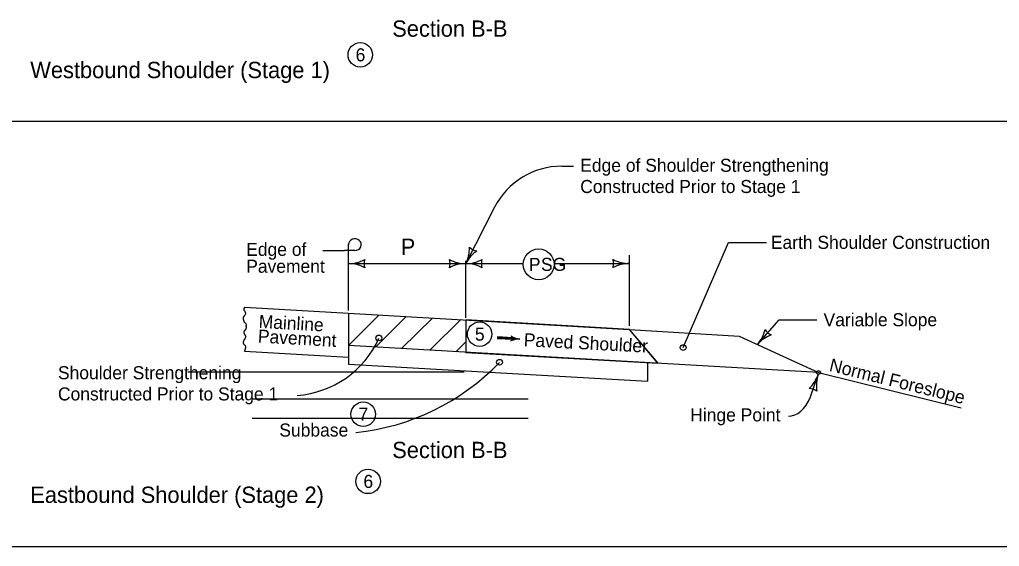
# Model space of a CAD drawing. Extents: x 6410 to 81668, y 3928 to 11667.
# Drawn here: x 7264 to 8465, y 8314 to 8961 of the extents above; entities that cross this region are included whole.
import ezdxf

# ---------------------------------------------------------------- set-up
doc = ezdxf.new("R2010")
doc.units = 0
for name, color, linetype in [('dsnNonPlotable', 7, 'Continuous'), ('dsnStdBlockModified', 7, 'Continuous'), ('dsnStdSection', 7, 'Continuous'), ('Level 11', 7, 'Continuous'), ('Level 14', 7, 'Continuous'), ('Level 3', 7, 'Continuous'), ('Level 7', 7, 'Continuous')]:
    doc.layers.add(name, color=color, linetype=linetype)

msp = doc.modelspace()

# ---------------------------------------------------------------- linework, layer by layer
at = {"layer": 'dsnNonPlotable'}
msp.add_line((6410.4, 8314.4), (9506.1, 8314.4), dxfattribs=at)
at = {"layer": 'dsnStdBlockModified'}
for p, q in [((7539.5, 8607.8), (7667, 8600.4)), ((7667, 8600.4), (7667, 8546.4)), ((7667, 8600.4), (8011.2, 8580.4)), ((7810.7, 8592.1), (7810.7, 8552.2)), ((8010.8, 8580.6), (8010.8, 8580.6)), ((8011.2, 8580.4), (8046.3, 8539)), ((8011.3, 8580.5), (8146, 8572.1)), ((8146, 8572.1), (8243.1, 8527.6)), ((7539.5, 8553.8), (7667, 8546.4)), ((8243.1, 8527.6), (7667, 8560.8)), ((8033.5, 8554.1), (8033.5, 8554.1)), ((7667, 8546.4), (7667, 8538)), ((7667, 8538), (8033.5, 8516.9)), ((8033.5, 8539.7), (8033.5, 8516.9)), ((7470.2, 8528.5), (7808.7, 8528.5)), ((8243.1, 8527.6), (8418, 8484.3)), ((7548.9, 8495.5), (7887.4, 8495.5)), ((7548.9, 8471.8), (7887.4, 8471.8))]:
    msp.add_line(p, q, dxfattribs=at)
msp.add_ellipse((8243.1, 8527.6), major_axis=(2.58, 0), ratio=0.913811, dxfattribs=at)
for points in [[(7539.5, 8607.8), (7539, 8604.2), (7540, 8602.7), (7540.9, 8600.4), (7540.3, 8598.4), (7538.4, 8596), (7537.9, 8594.1), (7538.4, 8591.8), (7539.2, 8589.4), (7540.3, 8588.7), (7541.7, 8586.2), (7541.7, 8585.3)], [(7539.7, 8568.2), (7539.9, 8568.5), (7540.1, 8568.7), (7540.5, 8569.3), (7540.7, 8569.9), (7540.9, 8570.2), (7541, 8570.5), (7541.1, 8571.1), (7541.1, 8571.7), (7541.1, 8572.3), (7541, 8572.6), (7541, 8572.7), (7541, 8572.9), (7540.7, 8573.2), (7540.5, 8573.6), (7540.2, 8574), (7539.9, 8574.4), (7539.8, 8574.7), (7539.6, 8574.9), (7539.4, 8575.5), (7539.2, 8576.1), (7539.1, 8576.4), (7539, 8576.7), (7539, 8576.8), (7539, 8576.9), (7539.2, 8577.7), (7539.4, 8578.2), (7539.7, 8578.7), (7540.1, 8579.4), (7540.6, 8579.9), (7541.1, 8580.5), (7541.4, 8580.8), (7541.6, 8581.1), (7541.8, 8581.6), (7541.9, 8582.1), (7542, 8582.5), (7542.1, 8582.8), (7542.1, 8582.9), (7542.1, 8583), (7542, 8583.5), (7541.9, 8584), (7541.8, 8584.2), (7541.8, 8584.3), (7541.7, 8584.4), (7541.7, 8584.5), (7541.7, 8585.3)], [(7539.7, 8568.2), (7539.5, 8568), (7539.2, 8567.8), (7539, 8567.5), (7538.8, 8567.2), (7538.7, 8567), (7538.5, 8566.7), (7538.3, 8566.1), (7538.2, 8565.8), (7538.1, 8565.5), (7538, 8565.2), (7538, 8565.1), (7538, 8564.9), (7538, 8564.4), (7538.1, 8563.9), (7538.3, 8563.4), (7538.6, 8562.9), (7539, 8562.2), (7539.5, 8561.7), (7540, 8561.2), (7540.3, 8560.8), (7540.5, 8560.5), (7540.9, 8559.6), (7541, 8559.1), (7541, 8558.6), (7541, 8558.3), (7540.9, 8558), (7540.9, 8557.7), (7540.8, 8557.5), (7540.5, 8556.3), (7540.3, 8555.7), (7540.1, 8555.1), (7539.9, 8554.5), (7539.7, 8554.2), (7539.6, 8553.9), (7539.5, 8553.8)]]:
    msp.add_spline(points, degree=3, dxfattribs=at)
at = {"layer": 'dsnStdSection'}
for p, q in [((7928.4, 8780.7), (7942.7, 8780.7)), ((7846.1, 8730.3), (7810.7, 8661.2)), ((7667, 8664.5), (7667, 8685.3)), ((8077.2, 8558.2), (8132.9, 8687.3)), ((8132.9, 8687.3), (8179.3, 8687.3)), ((7635.6, 8677.3), (7662.3, 8677.3)), ((7674.8, 8677.3), (7662.3, 8677.3)), ((8011.3, 8585), (8011.3, 8671.7)), ((7667, 8603.6), (7667, 8664.5)), ((7667, 8661.2), (7881.3, 8661.2)), ((7810.7, 8594.9), (7810.7, 8664.5)), ((7919.1, 8661.3), (8011.3, 8661.3)), ((7667, 8560.8), (7704.7, 8598.2)), ((7700, 8558.9), (7737.8, 8596.3)), ((7732.2, 8557.1), (7770, 8594.5)), ((7766.8, 8555.1), (7804.6, 8592.5)), ((8168.2, 8561.9), (8194.8, 8592.4)), ((8194.8, 8592.4), (8241.2, 8592.4)), ((7798.5, 8553.2), (7810.7, 8565.4)), ((7868, 8569.3), (7849.8, 8570.4)), ((7867.9, 8568.4), (7867.9, 8568.4)), ((7868, 8570.3), (7868, 8570.3)), ((8233.3, 8497.7), (8242.8, 8525.3))]:
    msp.add_line(p, q, dxfattribs=at)
for points in [[(7868, 8570.3), (7849.8, 8571.3), (7849.7, 8569.4), (7867.9, 8568.4), (7867.9, 8570), (7850.1, 8571.1), (7850, 8569.6), (7867.5, 8568.6), (7867.6, 8569.8), (7850.3, 8570.8), (7850.3, 8569.8), (7867.3, 8568.8), (7867.4, 8569.5), (7850.5, 8570.6), (7850.5, 8570), (7867.1, 8569.1)], [(7867.6, 8571.5), (7868.3, 8570.3), (7868.3, 8568.7), (7867.5, 8567.3), (7870.3, 8568.2), (7873.5, 8568.8), (7874.4, 8568.9), (7872.1, 8569.5), (7868.9, 8570.7), (7868, 8571.3), (7868.1, 8567.7), (7873, 8569), (7868.4, 8570.5), (7868.4, 8568.1), (7871.8, 8569.1), (7868.8, 8569.9), (7868.6, 8568.5), (7870.7, 8569), (7869.1, 8569.5), (7869, 8568.9), (7869.8, 8569)]]:
    msp.add_lwpolyline(points, dxfattribs=at)
msp.add_circle((7900.2, 8660.3), 18.9, dxfattribs=at)
for centre, radius, start, end in [((7928.4, 8688.3), 92.4, 90, 152.9341), ((7772.9, 8680.5), 42.5, 332.9341, 1.0066), ((7848.6, 8641.8), 42.5, 124.8616, 152.9341), ((7826.9, 8692.9), 16.4, 225.2008, 260.6675), ((7667, 8703.7), 42.5, 270, 298.0725), ((7667, 8618.7), 42.5, 61.9275, 90), ((7702.6, 8661.2), 16.4, 162.2666, 197.7334), ((7775.1, 8661.2), 16.4, 342.2666, 17.7334), ((7810.7, 8703.7), 42.5, 241.9275, 270), ((7810.7, 8618.7), 42.5, 90, 118.0725), ((7810.7, 8703.7), 42.5, 270, 298.0725), ((7810.7, 8618.7), 42.5, 61.9275, 90), ((7846.3, 8661.2), 16.4, 162.2666, 197.7334), ((7975.6, 8661.3), 16.4, 342.2666, 17.7333), ((8011.3, 8703.8), 42.5, 241.9275, 270), ((8011.3, 8618.8), 42.5, 90, 118.0725), ((8136.2, 8589.9), 42.5, 318.8454, 346.9178), ((8191.6, 8588.8), 16.4, 211.112, 246.5787), ((7595.7, 8618.2), 118.9, 274.0851, 336.0699), ((8200.2, 8534), 42.5, 110.7729, 138.8454), ((7648.2, 8734.9), 282, 275.6784, 316.2844), ((8202.6, 8539.1), 42.5, 312.9788, 341.0513), ((8283, 8511.5), 42.5, 161.0513, 189.1238), ((8231.2, 8491.6), 16.4, 53.3179, 88.7846)]:
    msp.add_arc(centre, radius, start, end, dxfattribs=at)
for centre, major_axis, ratio, start_param, end_param in [((7674.8, 8684.5), (-7.81, 0), 0.913811, 1.570796, 6.283185), ((7864.2, 8569.5), (3.88, 0), 0.913811, 5.202895, 7.237436), ((7876.5, 8548.5), (22.2, 0), 0.913811, 1.537172, 2.061295), ((7879.3, 8588.9), (-22.2, 0), 0.913811, 0.954258, 1.478381), ((8206.2, 8535.5), (0, 61.5), 0.559383, 3.141593, 4.048985)]:
    msp.add_ellipse(centre, major_axis=major_axis, ratio=ratio, start_param=start_param, end_param=end_param, dxfattribs=at)
at = {"layer": 'Level 11'}
msp.add_line((8566, 8835.4), (6410.4, 8835.4), dxfattribs=at)
at = {"layer": 'Level 14'}
for centre in [(7704.3, 8570), (7704.3, 8570), (8077.2, 8558.2), (8077.2, 8558.2), (7852.2, 8540.2), (7852.2, 8540.2)]:
    msp.add_circle(centre, 3.54, dxfattribs=at)
at = {"layer": 'Level 3'}
for p, q in [((7810.8, 8592.1), (7810.7, 8552.2)), ((8011.3, 8580.5), (7810.8, 8592.1)), ((8046.3, 8539), (8011.3, 8580.5)), ((7810.7, 8552.2), (8046.3, 8539))]:
    msp.add_line(p, q, dxfattribs=at)
at = {"layer": 'Level 7'}
for centre in [(7681.5, 8917.3), (7827.8, 8574.7), (7685.1, 8476.5), (7691.1, 8394.1)]:
    msp.add_circle(centre, 15, dxfattribs=at)

# ---------------------------------------------------------------- texts
at = {"layer": 'dsnStdSection'}
for s, height, p in [('Section B-B', 20, (7720.7, 8939.5)), ('Westbound Shoulder (Stage 1)', 20, (7277.1, 8888.7)), ('Edge of Shoulder Strengthening', 16, (7951.1, 8773.8)), ('Constructed Prior to Stage 1', 16, (7951.1, 8747.8)), ('Earth Shoulder Construction', 16, (8184.7, 8679.3)), ('Edge of ', 16, (7541.7, 8670.7)), ('P', 20, (7731.1, 8671.9)), ('Pavement', 16, (7541.7, 8650)), ('P', 16, (7888.1, 8652.3)), ('SG', 16, (7903, 8652.3)), ('Variable Slope', 16, (8249.3, 8584.4)), ('Shoulder Strengthening', 16, (7311, 8519.4)), ('Constructed Prior to Stage 1', 16, (7311, 8493.4)), ('Hinge Point', 16, (8085.9, 8467.7)), ('Subbase', 16, (7582.3, 8449.1)), ('Section B-B', 20, (7720.7, 8422.7)), ('Eastbound Shoulder (Stage 2)', 20, (7277.1, 8367.7))]:
    msp.add_text(s, height=height, dxfattribs=at).set_placement(p)
for s, rotation, p in [('Mainline', 356.7346, (7556.7, 8582.5)), ('Pavement', 356.7346, (7555.7, 8564.5)), ('Paved Shoulder ', 356.983, (7881.6, 8560)), ('Normal Foreslope', 346.0988, (8255.3, 8529.7))]:
    msp.add_text(s, height=16, rotation=rotation, dxfattribs=at).set_placement(p)
at = {"layer": 'Level 7'}
for s, p in [('6', (7675.8, 8909.3)), ('5', (7822, 8566.7)), ('7', (7679.4, 8468.5)), ('6', (7685.4, 8386.1))]:
    msp.add_text(s, height=16, dxfattribs=at).set_placement(p)

doc.saveas('drawing.dxf')
